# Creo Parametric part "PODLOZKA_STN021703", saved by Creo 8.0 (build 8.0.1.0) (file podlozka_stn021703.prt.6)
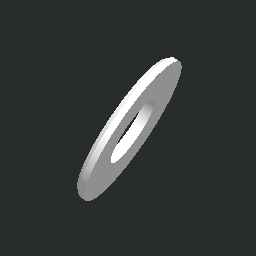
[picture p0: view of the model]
Units: Custom; MM, KILOGRAM, SECS
Materials in the file: OCEL_N

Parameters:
  KATEGORIE = "4"
  NAZOV = "PODLOZKA_STN021703"
  NORMA = "STN 02 1703"
  N1 = "ST"
  N2 = "T"
  PTC_MATERIAL_NAME = "OCEL_N"

Other parameters: HMOTNOST, HUSTOTA, HMOTNOST_1, D3

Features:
  1. chamfer

Other named items: S_00034, S_00039, S_00044, S_00046, S_00048, S_00050

Layers: BEZUGSACHSEN, BOHRUNGEN, KONSTRUKTIONSELEMENTE, NORMTEILE

Family table entries: PODLOZKA_3_2, PODLOZKA_STN021703, value(d_val), value(i_val), PODLOZKA_4_3, PODLOZKA_STN021703, 2/ , PODLOZKA_5_3, PODLOZKA_STN021703, 2/#, value(s_val), _PODLOZKA_5_3, .PRO_MP_CSYS, info(feat_list_rev_info), revision(mdl_geom_rev_detail_t_geomrev), info(tuples_list_rev_info), data(extra_mps), info(geom_item_rev_info), ._PODLOZKA_5_3, .PRO_MP_CSYS, PODLOZKA_6_4, PODLOZKA_STN021703, 2/&, PODLOZKA_8_4, PODLOZKA_STN021703, 2/,, PODLOZKA_10_5, PODLOZKA_STN021703, &/%, 2/2, PODLOZKA_13, PODLOZKA_STN021703, &/*, 2/4, PODLOZKA_17, PODLOZKA_STN021703, &/1, 2/;, PODLOZKA_21, PODLOZKA_STN021703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

Surfaces: 2 plane, 2 cylinder, 2 cone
